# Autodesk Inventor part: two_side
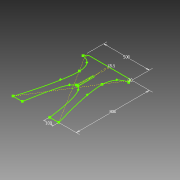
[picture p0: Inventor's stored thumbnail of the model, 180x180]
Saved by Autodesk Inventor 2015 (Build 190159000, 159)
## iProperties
Created: 2017-06
Part Number: two_side
Material: Generic
Document SubType Name: Modeling
Designer: mcalderon
Density: 1 g/cm^3
Appearance: Default
Author: mcalderon
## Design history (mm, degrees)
sketch "Sketch1"
  geometry: L1 (250, 364)-(250, 382); L2 (-250, -400)-(250, 400); L3 (250, -400)-(-250, 400); L4 (250, -400)-(150, -400); L5 (-250, 364)-(-250, 382); L6 (-8.5, 52)-(9.5, 400); L7 (9, 52)-(-9, 400); L8 (-9, 229.266)-(9.5, 229.266); L9 (230, 400)-(9.5, 400); L10 (-230, 400)-(-230, 382); L11 (230, 400)-(230, 382); L12 (-250, 382)-(-230, 382); L13 (230, 382)-(250, 382); L14 (-250, -400)-(-150, -400); L15 (-9, 400)-(-230, 400); L16 (9.5, 229.266)-(9.5, 49.813); L17 (-9, 229.266)-(-9, 49.989); L18 (-49.005, 36.237)-(31.005, 63.74); L19 (49.52, 35.511)-(-30.52, 64.116); L20 (-9, 400)-(9.5, 400); A1 r 52.245 centre (7.983, 0.582) between (20.59, 51.282) and (-33.132, 32.816); A2 r 43.853 centre (-5.258, 8.518) between (31.707, 32.111) and (-18.897, 50.196); 10 further points
  constraints: 40 end point, 6 midpoint, 2 centre point, 2 horizontal, 2 perpendicular, 2 point on circle, 2 vertical, 1 parallel, 1 point on line, 24 other
  dimensions: "d2" = 500 distance of L3.end L2.end; "d3" = 800 distance of L2.end L3.start; "d4" = 100 distance of L4.start L4.end; "d5" = 18.5 distance of L7.end L6.end; "d10" = 20 distance of L9.start L2.end
other parameters: "d7" = 18, "d8" = 18
